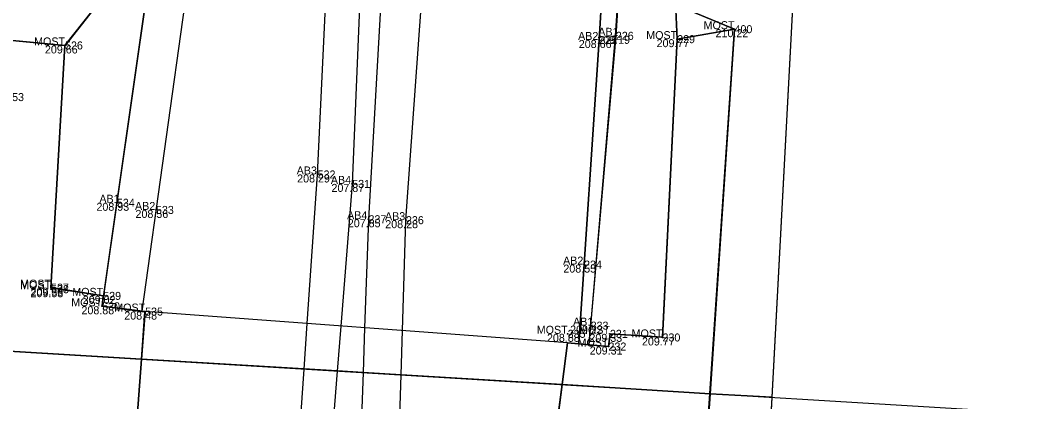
# Model space of a CAD drawing. Extents: x -263091 to -262565, y -1238731 to -1237092.
# Drawn here: x -262835.54 to -262810.24, y -1237934.9 to -1237925.36 of the extents above; entities that cross this region are included whole.
import ezdxf

# ---------------------------------------------------------------- set-up
doc = ezdxf.new("R2010")
doc.units = 0
for name, color, linetype in [('01_Hrana_betónu', 7, 'Continuous'), ('03_Asfalt', 7, 'Continuous'), ('04_Most', 7, 'Continuous'), ('05_Hrana_terénu', 7, 'Continuous'), ('09_Múrik', 7, 'Continuous'), ('10', 7, 'Continuous'), ('Groma (21)', 7, 'Continuous'), ('Groma (22)', 7, 'Continuous'), ('Groma (23)', 7, 'Continuous'), ('Groma (24)', 7, 'Continuous'), ('U003_Asfalt', 7, 'Continuous'), ('U003_Betónové_panely', 7, 'Continuous'), ('U003_Ostatné_plochy', 7, 'Continuous'), ('U004_Asfalty', 7, 'Continuous'), ('U004_Betónové_múriky', 7, 'Continuous'), ('U004_Betónové_panely', 7, 'Continuous'), ('U004_Ostatné_plochy', 7, 'Continuous'), ('U004_Zeleň_mimo', 7, 'Continuous'), ('U004_Zeleň_vnútro', 7, 'Continuous'), ('U004_Zeleň_zatrávňovač', 7, 'Continuous')]:
    doc.layers.add(name, color=color, linetype=linetype)

msp = doc.modelspace()

# ---------------------------------------------------------------- linework, layer by layer
at = {"layer": '01_Hrana_betónu'}
for p, q in [((-262832.416, -1237932.646), (-262832.51, -1237933.84)), ((-262822, -1237934.47), (-262821.859, -1237933.429)), ((-262832.51, -1237933.84), (-262832.64, -1237935.62)), ((-262822.231, -1237936.276), (-262822, -1237934.47))]:
    msp.add_line(p, q, dxfattribs=at)
for points in [[(-262833.49, -1237932.513), (-262832.358, -1237924.572), (-262831.993, -1237918.626), (-262831.904, -1237915.074), (-262831.439, -1237906.309), (-262830.324, -1237884.482), (-262828.859, -1237869.656), (-262826.973, -1237856.487), (-262824.752, -1237845.872), (-262820.768, -1237827.409), (-262815.971, -1237805.011), (-262811.874, -1237785.528), (-262810.073, -1237767.205), (-262809.465, -1237744.209), (-262809.348, -1237719.32), (-262807.762, -1237709.127), (-262805.583, -1237701.261), (-262801.096, -1237689.829), (-262795.064, -1237676.268)], [(-262794.181, -1237676.612), (-262800.21, -1237690.201), (-262804.735, -1237701.618), (-262806.814, -1237709.415), (-262808.46, -1237719.391), (-262808.589, -1237744.23), (-262809.169, -1237767.262), (-262810.977, -1237785.858), (-262815.119, -1237805.286), (-262819.878, -1237827.449), (-262823.898, -1237846.237), (-262826.14, -1237856.747), (-262827.996, -1237869.725), (-262829.453, -1237884.611), (-262830.572, -1237906.318), (-262830.909, -1237915.064), (-262831.044, -1237918.638), (-262831.379, -1237924.623), (-262832.499, -1237932.636), (-262832.416, -1237932.646)], [(-262828.366, -1237932.946), (-262828.106, -1237929.217), (-262827.649, -1237919.578), (-262827.369, -1237915.073), (-262826.968, -1237906.664), (-262825.835, -1237884.909), (-262824.318, -1237870.338), (-262822.252, -1237856.88), (-262820.394, -1237847.242), (-262816.344, -1237828.005), (-262811.527, -1237806.128), (-262807.485, -1237786.652), (-262805.817, -1237767.526), (-262804.904, -1237743.876), (-262804.544, -1237721.54), (-262802.773, -1237710.111), (-262800.948, -1237703.699), (-262796.578, -1237692.416), (-262790.297, -1237678.834), (-262789.671, -1237677.512)], [(-262788.862, -1237677.903), (-262789.612, -1237679.5), (-262795.758, -1237692.783), (-262800.102, -1237704.105), (-262801.904, -1237710.319), (-262803.638, -1237721.631), (-262804.041, -1237743.855), (-262804.886, -1237767.666), (-262806.567, -1237786.84), (-262810.653, -1237806.707), (-262815.575, -1237828.361), (-262819.614, -1237847.41), (-262821.404, -1237856.927), (-262823.638, -1237870.532), (-262825.083, -1237884.947), (-262826.299, -1237906.725), (-262827.242, -1237929.453), (-262827.527, -1237933.008)], [(-262788.441, -1237678.106), (-262789.499, -1237680.304), (-262796.488, -1237695.789), (-262799.561, -1237704.378), (-262801.599, -1237711.648), (-262803.17, -1237722.277), (-262803.523, -1237744.912), (-262804.331, -1237767.555), (-262806.033, -1237786.907), (-262810.428, -1237808.027), (-262815.321, -1237829.941), (-262818.5, -1237845.545), (-262820.865, -1237857.635), (-262822.962, -1237871.266), (-262824.386, -1237885.795), (-262825.49, -1237906.658), (-262826.835, -1237930.337), (-262826.931, -1237933.053)], [(-262825.987, -1237933.123), (-262825.899, -1237930.36), (-262825.137, -1237919.703), (-262824.89, -1237915.193), (-262824.65, -1237906.715), (-262823.596, -1237885.855), (-262822.137, -1237871.403), (-262820.061, -1237857.781), (-262817.692, -1237845.812), (-262814.459, -1237830.149), (-262809.645, -1237808.205), (-262805.191, -1237787.117), (-262803.484, -1237767.641), (-262802.568, -1237744.998), (-262802.266, -1237722.317), (-262800.862, -1237712.121), (-262798.805, -1237704.616), (-262795.791, -1237696.17), (-262788.393, -1237679.964), (-262787.674, -1237678.477)], [(-262828.445, -1237934.083), (-262828.366, -1237932.946)], [(-262827.527, -1237933.008), (-262827.618, -1237934.133)], [(-262826.931, -1237933.053), (-262826.971, -1237934.173)], [(-262826.022, -1237934.23), (-262825.987, -1237933.123)], [(-262828.571, -1237935.876), (-262828.445, -1237934.083)], [(-262827.618, -1237934.133), (-262827.762, -1237935.927)], [(-262826.971, -1237934.173), (-262827.034, -1237935.973)], [(-262826.079, -1237936.033), (-262826.022, -1237934.23)]]:
    msp.add_lwpolyline(points, dxfattribs=at)
at = {"layer": '03_Asfalt'}
for points in [[(-262814.5, -1237895.481), (-262815.119, -1237905.177), (-262816.001, -1237920.483), (-262816.76, -1237934.791)], [(-262816.76, -1237934.791), (-262817.067, -1237940.584), (-262818.198, -1237960.603), (-262819.351, -1237980.318), (-262820.259, -1237997.242), (-262821.106, -1238014.516), (-262822.726, -1238037.787), (-262824.929, -1238056.475), (-262826.695, -1238065.295), (-262832.135, -1238081.046), (-262834.142, -1238085.994), (-262836.111, -1238090.171)]]:
    msp.add_lwpolyline(points, dxfattribs=at)
at = {"layer": '04_Most'}
for points in [[(-262818.304, -1237934.697), (-262817.69, -1237925.584), (-262819.123, -1237925.833), (-262819.489, -1237933.293), (-262820.803, -1237933.203), (-262820.839, -1237933.52), (-262821.859, -1237933.429), (-262832.416, -1237932.646), (-262833.49, -1237932.513), (-262833.464, -1237932.253), (-262834.768, -1237932.047), (-262834.418, -1237925.991), (-262837.149, -1237925.733), (-262837.354, -1237927.143), (-262835.889, -1237927.282), (-262836.391, -1237933.13), (-262837.42, -1237933.072), (-262837.476, -1237933.537)], [(-262837.476, -1237933.537), (-262837.588, -1237934.475), (-262836.324, -1237934.594), (-262836.292, -1237935.17), (-262835.062, -1237935.275), (-262834.664, -1237935.731), (-262834.562, -1237935.803), (-262833.682, -1237935.77), (-262833.657, -1237935.467), (-262832.64, -1237935.62), (-262822.231, -1237936.276), (-262821.226, -1237936.393), (-262821.088, -1237936.694), (-262819.91, -1237936.875), (-262819.871, -1237937.657), (-262818.511, -1237937.77), (-262818.304, -1237934.697)]]:
    msp.add_lwpolyline(points, dxfattribs=at)
at = {"layer": '05_Hrana_terénu'}
for points in [[(-262819.123, -1237925.833), (-262819.193, -1237924.361), (-262818.874, -1237915.472), (-262818.289, -1237906.84), (-262817.033, -1237886.241), (-262815.506, -1237871.209), (-262813.693, -1237857.604), (-262811.493, -1237846.649), (-262808.389, -1237831.401), (-262803.328, -1237809.401), (-262799.108, -1237788.219), (-262797.264, -1237767.972), (-262796.32, -1237745.233), (-262795.609, -1237723.113), (-262794.587, -1237714.488), (-262792.775, -1237707.13), (-262790.198, -1237699.936), (-262783.238, -1237683.427), (-262781.933, -1237681.667), (-262781.499, -1237681.254)], [(-262833.13, -1237919.565), (-262833.486, -1237924.805), (-262834.418, -1237925.991)]]:
    msp.add_lwpolyline(points, dxfattribs=at)
at = {"layer": '09_Múrik'}
for points in [[(-262819.991, -1237915.564), (-262820.655, -1237925.75), (-262821.327, -1237933.476)], [(-262821.581, -1237933.453), (-262821.074, -1237925.854), (-262820.488, -1237916.085)]]:
    msp.add_lwpolyline(points, dxfattribs=at)
at = {"layer": '10'}
msp.add_line((-262851.323, -1237932.698), (-262791.061, -1237936.346), dxfattribs=at)
at = {"layer": 'Groma (21)'}
for centre in [(-262817.69, -1237925.584), (-262821.074, -1237925.854), (-262820.655, -1237925.75), (-262819.123, -1237925.833), (-262834.418, -1237925.991), (-262828.106, -1237929.217), (-262827.242, -1237929.453), (-262833.121, -1237929.925), (-262832.145, -1237930.104), (-262826.835, -1237930.337), (-262825.899, -1237930.36), (-262821.449, -1237931.471), (-262834.768, -1237932.047), (-262834.767, -1237932.086), (-262833.464, -1237932.253), (-262833.49, -1237932.513), (-262832.416, -1237932.646), (-262821.859, -1237933.202), (-262821.285, -1237932.998), (-262820.803, -1237933.203), (-262819.489, -1237933.293), (-262820.839, -1237933.52)]:
    msp.add_circle(centre, 0.01, dxfattribs=at)
at = {"layer": 'U003_Asfalt'}
msp.add_lwpolyline([(-262818.51, -1237937.77), (-262818.3, -1237934.7), (-262816.76, -1237934.79), (-262817.07, -1237940.58)], dxfattribs=at)
msp.add_lwpolyline([(-262818.51, -1237937.77), (-262818.3, -1237934.7), (-262816.76, -1237934.79), (-262817.07, -1237940.58)], dxfattribs=at)
at = {"layer": 'U003_Betónové_panely'}
msp.add_lwpolyline([(-262832.64, -1237935.62), (-262832.51, -1237933.84), (-262828.45, -1237934.08), (-262827.62, -1237934.13), (-262826.97, -1237934.17), (-262826.02, -1237934.23), (-262822, -1237934.47), (-262822.23, -1237936.28)], dxfattribs=at)
msp.add_lwpolyline([(-262832.64, -1237935.62), (-262832.51, -1237933.84), (-262828.45, -1237934.08), (-262827.62, -1237934.13), (-262826.97, -1237934.17), (-262826.02, -1237934.23), (-262822, -1237934.47), (-262822.23, -1237936.28)], dxfattribs=at)
at = {"layer": 'U003_Ostatné_plochy'}
for points in [[(-262832.51, -1237933.84), (-262832.64, -1237935.62), (-262833.66, -1237935.47), (-262833.68, -1237935.77), (-262834.56, -1237935.8), (-262834.66, -1237935.73), (-262835.06, -1237935.28), (-262836.29, -1237935.17), (-262836.32, -1237934.59), (-262837.59, -1237934.48), (-262837.48, -1237933.54)], [(-262818.3, -1237934.7), (-262818.51, -1237937.77), (-262819.87, -1237937.66), (-262819.91, -1237936.88), (-262821.09, -1237936.69), (-262821.23, -1237936.39), (-262822.23, -1237936.28), (-262822, -1237934.47)]]:
    msp.add_lwpolyline(points, close=True, dxfattribs=at)
for points in [[(-262834.56, -1237935.8), (-262834.66, -1237935.73), (-262835.06, -1237935.28), (-262836.29, -1237935.17), (-262836.32, -1237934.59), (-262837.59, -1237934.48), (-262837.48, -1237933.54), (-262832.51, -1237933.84), (-262832.64, -1237935.62), (-262833.66, -1237935.47), (-262833.68, -1237935.77), (-262834.56, -1237935.8)], [(-262818.51, -1237937.77), (-262819.87, -1237937.66), (-262819.91, -1237936.88), (-262821.09, -1237936.69), (-262821.23, -1237936.39), (-262822.23, -1237936.28), (-262822, -1237934.47), (-262818.3, -1237934.7), (-262818.51, -1237937.77)]]:
    msp.add_lwpolyline(points, dxfattribs=at)
at = {"layer": 'U004_Asfalty'}
msp.add_lwpolyline([(-262818.76, -1237925.14), (-262818.37, -1237915.57), (-262817.69, -1237906.99), (-262816.95, -1237895.23), (-262814.5, -1237895.48), (-262815.12, -1237905.18), (-262816, -1237920.48), (-262816.76, -1237934.79), (-262818.3, -1237934.7), (-262817.69, -1237925.58)], close=True, dxfattribs=at)
msp.add_lwpolyline([(-262816.76, -1237934.79), (-262818.3, -1237934.7), (-262817.69, -1237925.58), (-262818.76, -1237925.14), (-262818.37, -1237915.57), (-262817.69, -1237906.99), (-262816.95, -1237895.23), (-262814.5, -1237895.48), (-262815.12, -1237905.18), (-262816, -1237920.48), (-262816.76, -1237934.79)], dxfattribs=at)
at = {"layer": 'U004_Betónové_múriky'}
msp.add_lwpolyline([(-262820.66, -1237925.75), (-262821.33, -1237933.48), (-262821.58, -1237933.45), (-262821.07, -1237925.85), (-262820.49, -1237916.09), (-262819.99, -1237915.56)], close=True, dxfattribs=at)
msp.add_lwpolyline([(-262821.33, -1237933.48), (-262821.58, -1237933.45), (-262821.07, -1237925.85), (-262820.49, -1237916.09), (-262819.99, -1237915.56), (-262820.66, -1237925.75), (-262821.33, -1237933.48)], dxfattribs=at)
at = {"layer": 'U004_Betónové_panely'}
for points in [[(-262796.11, -1237713.49), (-262797.35, -1237722.8), (-262798.01, -1237745.03), (-262799, -1237767.83), (-262800.84, -1237788.07), (-262805.17, -1237808.9), (-262810.05, -1237831.05), (-262813.21, -1237846.37), (-262815.44, -1237858.03), (-262817.52, -1237871.5), (-262819.01, -1237885.89), (-262819.76, -1237906.84), (-262819.99, -1237915.56), (-262820.49, -1237916.09), (-262821.07, -1237925.85), (-262821.58, -1237933.45), (-262821.86, -1237933.43), (-262822, -1237934.47)], [(-262822, -1237934.47), (-262826.02, -1237934.23), (-262826.97, -1237934.17), (-262827.62, -1237934.13), (-262828.45, -1237934.08), (-262832.51, -1237933.84), (-262832.42, -1237932.65), (-262832.5, -1237932.64), (-262833.49, -1237932.51), (-262832.36, -1237924.57), (-262831.99, -1237918.63), (-262831.9, -1237915.07), (-262831.44, -1237906.31), (-262830.32, -1237884.48), (-262828.86, -1237869.66), (-262826.97, -1237856.49), (-262824.75, -1237845.87), (-262820.77, -1237827.41), (-262815.97, -1237805.01), (-262811.87, -1237785.53), (-262810.07, -1237767.21), (-262809.47, -1237744.21), (-262809.35, -1237719.32)], [(-262817.52, -1237871.5), (-262819.01, -1237885.89), (-262819.76, -1237906.84), (-262819.99, -1237915.56), (-262820.49, -1237916.09), (-262821.07, -1237925.85), (-262821.58, -1237933.45), (-262821.86, -1237933.43), (-262822, -1237934.47), (-262826.02, -1237934.23), (-262826.97, -1237934.17), (-262827.62, -1237934.13), (-262828.45, -1237934.08), (-262832.51, -1237933.84), (-262832.42, -1237932.65), (-262832.5, -1237932.64), (-262833.49, -1237932.51), (-262832.36, -1237924.57), (-262831.99, -1237918.63), (-262831.9, -1237915.07), (-262831.44, -1237906.31), (-262830.32, -1237884.48), (-262828.86, -1237869.66)]]:
    msp.add_lwpolyline(points, dxfattribs=at)
at = {"layer": 'U004_Ostatné_plochy'}
for points in [[(-262818.3, -1237934.7), (-262822, -1237934.47), (-262821.86, -1237933.43), (-262820.84, -1237933.52), (-262820.8, -1237933.2), (-262819.49, -1237933.29), (-262819.12, -1237925.83), (-262817.69, -1237925.58)], [(-262837.48, -1237933.54), (-262837.42, -1237933.07), (-262836.39, -1237933.13), (-262835.89, -1237927.28), (-262837.35, -1237927.14), (-262837.15, -1237925.73), (-262834.42, -1237925.99), (-262834.77, -1237932.05), (-262833.46, -1237932.25), (-262833.49, -1237932.51), (-262832.42, -1237932.65), (-262832.51, -1237933.84)]]:
    msp.add_lwpolyline(points, close=True, dxfattribs=at)
for points in [[(-262818.3, -1237934.7), (-262822, -1237934.47), (-262821.86, -1237933.43), (-262820.84, -1237933.52), (-262820.8, -1237933.2), (-262819.49, -1237933.29), (-262819.12, -1237925.83), (-262817.69, -1237925.58), (-262818.3, -1237934.7)], [(-262832.51, -1237933.84), (-262837.48, -1237933.54), (-262837.42, -1237933.07), (-262836.39, -1237933.13), (-262835.89, -1237927.28), (-262837.35, -1237927.14), (-262837.15, -1237925.73), (-262834.42, -1237925.99), (-262834.77, -1237932.05), (-262833.46, -1237932.25), (-262833.49, -1237932.51), (-262832.42, -1237932.65), (-262832.51, -1237933.84)]]:
    msp.add_lwpolyline(points, dxfattribs=at)
at = {"layer": 'U004_Zeleň_mimo'}
msp.add_lwpolyline([(-262831.15, -1237869.34), (-262832.73, -1237884.62), (-262833.81, -1237906.28), (-262834.02, -1237915.3), (-262834.34, -1237921.2), (-262833.49, -1237924.81), (-262834.42, -1237925.99), (-262837.15, -1237925.73), (-262837.41, -1237925.56), (-262839.28, -1237924.72), (-262838.95, -1237919.22), (-262848.49, -1237918.39), (-262860.57, -1237917.21), (-262859.39, -1237895.81), (-262865.89, -1237895.46), (-262864.07, -1237848.35)], dxfattribs=at)
at = {"layer": 'U004_Zeleň_vnútro'}
for points in [[(-262819.12, -1237925.83), (-262819.19, -1237924.36), (-262818.87, -1237915.47), (-262818.29, -1237906.84), (-262817.03, -1237886.24), (-262815.51, -1237871.21), (-262813.69, -1237857.6), (-262811.49, -1237846.65), (-262808.39, -1237831.4), (-262803.33, -1237809.4), (-262799.11, -1237788.22), (-262797.26, -1237767.97), (-262796.32, -1237745.23), (-262795.61, -1237723.11), (-262794.59, -1237714.49)], [(-262793.68, -1237714.79), (-262794.85, -1237723.2), (-262795.7, -1237745.3), (-262796.56, -1237768.08), (-262798.72, -1237788.19), (-262802.85, -1237809.45), (-262807.53, -1237831.59), (-262810.76, -1237846.83), (-262812.84, -1237857.76), (-262814.89, -1237871.13), (-262816.32, -1237886.18), (-262816.95, -1237895.23), (-262817.69, -1237906.99), (-262818.37, -1237915.57), (-262818.76, -1237925.14), (-262817.69, -1237925.58), (-262819.12, -1237925.83)], [(-262802.85, -1237809.45), (-262807.53, -1237831.59), (-262810.76, -1237846.83), (-262812.84, -1237857.76), (-262814.89, -1237871.13), (-262816.32, -1237886.18), (-262816.95, -1237895.23), (-262817.69, -1237906.99), (-262818.37, -1237915.57), (-262818.76, -1237925.14), (-262817.69, -1237925.58), (-262819.12, -1237925.83), (-262819.19, -1237924.36), (-262818.87, -1237915.47), (-262818.29, -1237906.84), (-262817.03, -1237886.24), (-262815.51, -1237871.21), (-262813.69, -1237857.6), (-262811.49, -1237846.65), (-262808.39, -1237831.4), (-262803.33, -1237809.4)]]:
    msp.add_lwpolyline(points, dxfattribs=at)
at = {"layer": 'U004_Zeleň_zatrávňovač'}
for points in [[(-262820.84, -1237933.52), (-262821.33, -1237933.48), (-262821.28, -1237933), (-262820.66, -1237925.75), (-262819.99, -1237915.56), (-262819.76, -1237906.84), (-262819.01, -1237885.89), (-262817.52, -1237871.5), (-262815.44, -1237858.03), (-262813.21, -1237846.37), (-262810.05, -1237831.05), (-262805.17, -1237808.9), (-262800.84, -1237788.07), (-262799, -1237767.83), (-262798.01, -1237745.03), (-262797.35, -1237722.8), (-262796.11, -1237713.49)], [(-262794.59, -1237714.49), (-262795.61, -1237723.11), (-262796.32, -1237745.23), (-262797.26, -1237767.97), (-262799.11, -1237788.22), (-262803.33, -1237809.4), (-262808.39, -1237831.4), (-262811.49, -1237846.65), (-262813.69, -1237857.6), (-262815.51, -1237871.21), (-262817.03, -1237886.24), (-262818.29, -1237906.84), (-262818.87, -1237915.47), (-262819.19, -1237924.36), (-262819.12, -1237925.83), (-262819.49, -1237933.29), (-262820.8, -1237933.2), (-262820.84, -1237933.52)], [(-262803.33, -1237809.4), (-262808.39, -1237831.4), (-262811.49, -1237846.65), (-262813.69, -1237857.6), (-262815.51, -1237871.21), (-262817.03, -1237886.24), (-262818.29, -1237906.84), (-262818.87, -1237915.47), (-262819.19, -1237924.36), (-262819.12, -1237925.83), (-262819.49, -1237933.29), (-262820.8, -1237933.2), (-262820.84, -1237933.52), (-262821.33, -1237933.48), (-262821.28, -1237933), (-262820.66, -1237925.75), (-262819.99, -1237915.56), (-262819.76, -1237906.84), (-262819.01, -1237885.89), (-262817.52, -1237871.5), (-262815.44, -1237858.03), (-262813.21, -1237846.37), (-262810.05, -1237831.05), (-262805.17, -1237808.9)], [(-262833.46, -1237932.25), (-262834.77, -1237932.05), (-262834.42, -1237925.99), (-262833.49, -1237924.81), (-262833.13, -1237919.57), (-262831.99, -1237918.63), (-262832.36, -1237924.57), (-262833.46, -1237932.25)]]:
    msp.add_lwpolyline(points, dxfattribs=at)
msp.add_lwpolyline([(-262834.42, -1237925.99), (-262833.49, -1237924.81), (-262833.13, -1237919.57), (-262831.99, -1237918.63), (-262832.36, -1237924.57), (-262833.46, -1237932.25), (-262834.77, -1237932.05)], close=True, dxfattribs=at)

# ---------------------------------------------------------------- texts
at = {"layer": 'Groma (22)'}
for s, p in [('400', (-262817.69, -1237925.684)), ('526', (-262834.418, -1237926.091)), ('225', (-262821.074, -1237925.954)), ('226', (-262820.655, -1237925.85)), ('229', (-262819.123, -1237925.933)), ('553', (-262835.889, -1237927.382)), ('532', (-262828.106, -1237929.317)), ('531', (-262827.242, -1237929.553)), ('534', (-262833.121, -1237930.025)), ('533', (-262832.145, -1237930.204)), ('237', (-262826.835, -1237930.437)), ('236', (-262825.899, -1237930.46)), ('234', (-262821.449, -1237931.571)), ('527', (-262834.768, -1237932.147)), ('528', (-262834.767, -1237932.186)), ('529', (-262833.464, -1237932.353)), ('530', (-262833.49, -1237932.613)), ('535', (-262832.416, -1237932.746)), ('233', (-262821.285, -1237933.098)), ('235', (-262821.859, -1237933.302)), ('231', (-262820.803, -1237933.303)), ('230', (-262819.489, -1237933.393)), ('232', (-262820.839, -1237933.62))]:
    msp.add_text(s, height=0.2, dxfattribs=at).set_placement(p)
at = {"layer": 'Groma (23)'}
for s, p in [('210.22', (-262818.163, -1237925.784)), ('208.66', (-262821.581, -1237926.054)), ('209.19', (-262821.119, -1237925.95)), ('209.77', (-262819.636, -1237926.033)), ('209.66', (-262834.92, -1237926.191)), ('208.29', (-262828.618, -1237929.417)), ('207.87', (-262827.76, -1237929.653)), ('208.93', (-262833.633, -1237930.125)), ('208.56', (-262832.657, -1237930.304)), ('207.85', (-262827.352, -1237930.537)), ('208.28', (-262826.416, -1237930.56)), ('208.55', (-262821.966, -1237931.671)), ('209.58', (-262835.28, -1237932.247)), ('209.53', (-262835.279, -1237932.286)), ('209.02', (-262833.975, -1237932.453)), ('208.88', (-262834.007, -1237932.713)), ('208.48', (-262832.937, -1237932.846)), ('208.88', (-262822.376, -1237933.402)), ('209.22', (-262821.797, -1237933.198)), ('209.33', (-262821.315, -1237933.403)), ('209.77', (-262820.002, -1237933.493)), ('209.31', (-262821.307, -1237933.72))]:
    msp.add_text(s, height=0.2, dxfattribs=at).set_placement(p)
at = {"layer": 'Groma (24)'}
for s, p in [('MOST', (-262818.462, -1237925.584)), ('AB1', (-262821.093, -1237925.75)), ('MOST', (-262819.895, -1237925.833)), ('MOST', (-262835.19, -1237925.991)), ('AB2', (-262821.598, -1237925.854)), ('AB3', (-262828.63, -1237929.217)), ('AB4', (-262827.776, -1237929.453)), ('AB1', (-262833.559, -1237929.925)), ('AB2', (-262832.669, -1237930.104)), ('AB4', (-262827.369, -1237930.337)), ('AB3', (-262826.423, -1237930.36)), ('AB2', (-262821.973, -1237931.471)), ('MOST', (-262835.54, -1237932.047)), ('MOST', (-262835.539, -1237932.086)), ('MOST', (-262834.236, -1237932.253)), ('MOST', (-262834.262, -1237932.513)), ('MOST', (-262833.188, -1237932.646)), ('AB1', (-262821.723, -1237932.998)), ('MOST', (-262822.631, -1237933.202)), ('MOST', (-262821.575, -1237933.203)), ('MOST', (-262820.261, -1237933.293)), ('MOST', (-262821.611, -1237933.52))]:
    msp.add_text(s, height=0.2, dxfattribs=at).set_placement(p)

doc.saveas('drawing.dxf')
